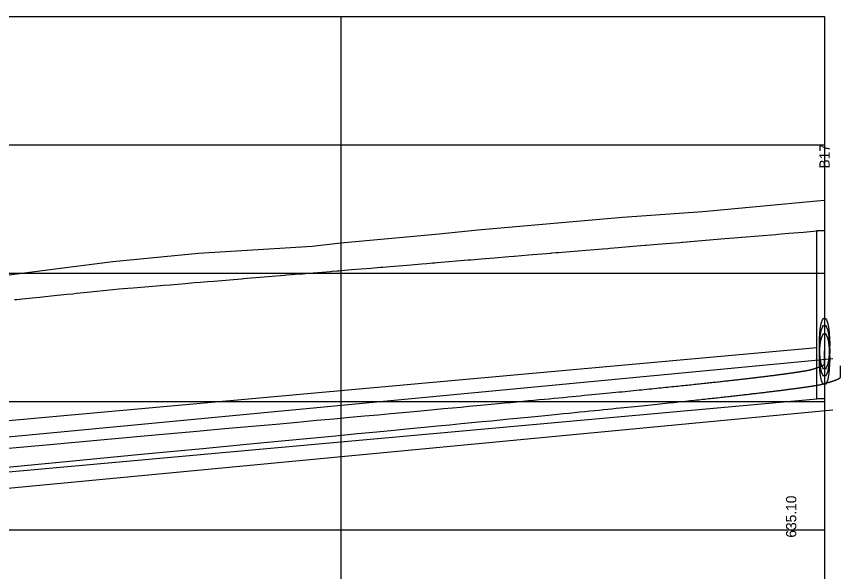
# Model space of a CAD drawing. Extents: x 2253035 to 2279930, y 13774972 to 13793443.
# Drawn here: x 2261163.2 to 2261323.8, y 13791365.4 to 13791473.6 of the extents above; entities that cross this region are included whole.
import ezdxf

# ---------------------------------------------------------------- set-up
doc = ezdxf.new("R2010")
doc.units = 0
for name, color, linetype in [('Default', 7, 'Continuous'), ('E_Utility_ATT_HH', 7, 'Continuous'), ('E_Utility_ATT_PR_PVC', 7, 'Continuous'), ('E_Utillity_Water_Water Line_12in', 7, 'Continuous'), ('E_Utillity_Water_Water Line_1in', 7, 'Continuous'), ('E_Utillity_Water_Water Line_4in', 7, 'Continuous'), ('E_Utillity_Water_Water Line_8in', 7, 'Continuous')]:
    doc.layers.add(name, color=color, linetype=linetype)

msp = doc.modelspace()

# ---------------------------------------------------------------- linework, layer by layer
at = {"layer": 'Default'}
for p, q in [((2261226.46, 13791298.56), (2261226.46, 13791473.56)), ((2260026.46, 13791448.56), (2261320.64, 13791448.56)), ((2260026.46, 13791423.56), (2261320.64, 13791423.56)), ((2260026.46, 13791398.56), (2261320.64, 13791398.56)), ((2260026.46, 13791373.56), (2261320.64, 13791373.56))]:
    msp.add_line(p, q, dxfattribs=at)
msp.add_lwpolyline([(2260026.46, 13791298.56), (2260026.46, 13791473.56), (2261320.64, 13791473.56), (2261320.64, 13791298.56)], close=True, dxfattribs=at)
at = {"layer": 'E_Utility_ATT_PR_PVC'}
for points in [[(2261151.51, 13791388.53), (2261169, 13791390.11), (2261181.06, 13791391.2), (2261190.23, 13791392.03), (2261197.64, 13791392.7), (2261203.84, 13791393.27), (2261209.16, 13791393.75), (2261213.82, 13791394.17), (2261217.97, 13791394.55), (2261221.7, 13791394.89), (2261225.08, 13791395.2), (2261228.18, 13791395.49), (2261231.04, 13791395.75), (2261233.69, 13791395.99), (2261236.15, 13791396.22), (2261238.46, 13791396.43), (2261240.63, 13791396.63), (2261242.67, 13791396.82), (2261244.59, 13791397), (2261246.42, 13791397.17), (2261248.16, 13791397.33), (2261249.81, 13791397.48), (2261251.38, 13791397.63), (2261252.89, 13791397.77), (2261254.33, 13791397.91), (2261255.71, 13791398.03), (2261257.04, 13791398.16), (2261258.31, 13791398.28), (2261259.54, 13791398.39), (2261260.73, 13791398.51), (2261261.87, 13791398.61), (2261262.97, 13791398.72), (2261264.04, 13791398.82), (2261265.07, 13791398.92), (2261266.07, 13791399.01), (2261267.03, 13791399.1), (2261267.97, 13791399.19), (2261268.88, 13791399.28), (2261269.77, 13791399.36), (2261270.63, 13791399.45), (2261271.46, 13791399.53), (2261272.28, 13791399.61), (2261273.07, 13791399.68), (2261273.84, 13791399.76), (2261274.59, 13791399.83), (2261275.33, 13791399.9), (2261276.04, 13791399.97), (2261276.74, 13791400.04), (2261277.42, 13791400.1), (2261278.08, 13791400.17), (2261278.73, 13791400.23), (2261279.37, 13791400.29), (2261279.99, 13791400.35), (2261280.6, 13791400.41), (2261281.19, 13791400.47), (2261281.78, 13791400.53), (2261282.35, 13791400.59), (2261282.9, 13791400.64), (2261283.45, 13791400.7), (2261283.99, 13791400.75), (2261284.51, 13791400.8), (2261285.02, 13791400.85), (2261285.53, 13791400.9), (2261286.02, 13791400.95), (2261286.51, 13791401), (2261286.99, 13791401.05), (2261287.45, 13791401.1), (2261287.91, 13791401.14), (2261288.36, 13791401.19), (2261288.81, 13791401.23), (2261289.24, 13791401.28), (2261289.67, 13791401.32), (2261290.09, 13791401.36), (2261290.5, 13791401.41), (2261290.91, 13791401.45), (2261291.31, 13791401.49), (2261291.7, 13791401.53), (2261292.09, 13791401.57), (2261292.47, 13791401.61), (2261292.84, 13791401.65), (2261293.21, 13791401.68), (2261293.57, 13791401.72), (2261293.92, 13791401.76), (2261294.28, 13791401.8), (2261294.62, 13791401.83), (2261294.96, 13791401.87), (2261295.29, 13791401.9), (2261295.62, 13791401.94), (2261295.95, 13791401.97), (2261296.27, 13791402), (2261296.58, 13791402.04), (2261296.89, 13791402.07), (2261297.2, 13791402.1), (2261297.5, 13791402.14), (2261297.8, 13791402.17), (2261298.09, 13791402.2), (2261298.38, 13791402.23), (2261298.66, 13791402.26), (2261298.94, 13791402.29), (2261299.22, 13791402.32), (2261299.49, 13791402.35), (2261299.76, 13791402.38), (2261300.02, 13791402.41), (2261300.29, 13791402.44), (2261300.54, 13791402.46), (2261300.8, 13791402.49), (2261301.05, 13791402.52), (2261301.3, 13791402.55), (2261301.54, 13791402.57), (2261301.78, 13791402.6), (2261302.02, 13791402.63), (2261302.26, 13791402.65), (2261302.49, 13791402.68), (2261302.72, 13791402.7), (2261302.94, 13791402.73), (2261303.17, 13791402.76), (2261303.39, 13791402.78), (2261303.6, 13791402.8), (2261303.82, 13791402.83), (2261304.03, 13791402.85), (2261304.24, 13791402.88), (2261304.45, 13791402.9), (2261304.65, 13791402.92), (2261304.85, 13791402.95), (2261305.05, 13791402.97), (2261305.25, 13791402.99), (2261305.44, 13791403.02), (2261305.63, 13791403.04), (2261305.82, 13791403.06), (2261306.01, 13791403.08), (2261306.2, 13791403.1), (2261306.38, 13791403.12), (2261306.56, 13791403.15), (2261306.74, 13791403.17), (2261306.91, 13791403.19), (2261307.09, 13791403.21), (2261307.26, 13791403.23), (2261307.43, 13791403.25), (2261307.6, 13791403.27), (2261307.76, 13791403.29), (2261307.93, 13791403.31), (2261308.09, 13791403.33), (2261308.25, 13791403.35), (2261308.41, 13791403.37), (2261308.57, 13791403.39), (2261308.72, 13791403.41), (2261308.87, 13791403.42), (2261309.03, 13791403.44), (2261309.18, 13791403.46), (2261309.32, 13791403.48), (2261309.47, 13791403.5), (2261309.61, 13791403.52), (2261309.76, 13791403.53), (2261309.9, 13791403.55), (2261310.04, 13791403.57), (2261310.18, 13791403.59), (2261310.31, 13791403.6), (2261310.45, 13791403.62), (2261310.58, 13791403.64), (2261310.71, 13791403.65), (2261310.84, 13791403.67), (2261310.97, 13791403.69), (2261311.1, 13791403.7), (2261311.23, 13791403.72), (2261311.35, 13791403.74), (2261311.47, 13791403.75), (2261311.6, 13791403.77), (2261311.72, 13791403.79), (2261311.84, 13791403.8), (2261311.95, 13791403.82), (2261312.07, 13791403.83), (2261312.19, 13791403.85), (2261312.3, 13791403.86), (2261312.41, 13791403.88), (2261312.53, 13791403.89), (2261312.64, 13791403.91), (2261312.75, 13791403.92), (2261312.85, 13791403.94), (2261312.96, 13791403.95), (2261313.07, 13791403.97), (2261313.17, 13791403.98), (2261313.27, 13791404), (2261313.38, 13791404.01), (2261313.48, 13791404.02), (2261313.58, 13791404.04), (2261313.68, 13791404.05), (2261313.77, 13791404.06), (2261313.87, 13791404.08), (2261313.97, 13791404.09), (2261314.06, 13791404.11), (2261314.15, 13791404.12), (2261314.25, 13791404.13), (2261314.34, 13791404.15), (2261314.43, 13791404.16), (2261314.52, 13791404.17), (2261314.61, 13791404.18), (2261314.69, 13791404.2), (2261314.78, 13791404.21), (2261314.86, 13791404.22), (2261314.95, 13791404.24), (2261315.03, 13791404.25), (2261315.12, 13791404.26), (2261315.2, 13791404.27), (2261315.28, 13791404.29), (2261315.36, 13791404.3), (2261315.44, 13791404.31), (2261315.52, 13791404.32), (2261315.59, 13791404.33), (2261315.67, 13791404.35), (2261315.75, 13791404.36), (2261315.82, 13791404.37), (2261315.89, 13791404.38), (2261315.97, 13791404.39), (2261316.04, 13791404.4), (2261316.11, 13791404.42), (2261316.18, 13791404.43), (2261316.25, 13791404.44), (2261316.32, 13791404.45), (2261316.39, 13791404.46), (2261316.46, 13791404.47), (2261316.52, 13791404.48), (2261316.59, 13791404.49), (2261316.66, 13791404.5), (2261316.72, 13791404.52), (2261316.78, 13791404.53), (2261316.85, 13791404.54), (2261316.91, 13791404.55), (2261316.97, 13791404.56), (2261317.03, 13791404.57), (2261317.09, 13791404.58), (2261317.15, 13791404.59), (2261317.21, 13791404.6), (2261317.27, 13791404.61), (2261317.33, 13791404.62), (2261317.38, 13791404.63), (2261317.44, 13791404.64), (2261317.5, 13791404.65), (2261317.55, 13791404.66), (2261317.6, 13791404.67), (2261317.66, 13791404.68), (2261317.71, 13791404.7), (2261317.76, 13791404.71), (2261317.81, 13791404.72), (2261317.87, 13791404.74), (2261317.92, 13791404.75), (2261317.97, 13791404.77), (2261318.02, 13791404.78), (2261318.06, 13791404.79), (2261318.11, 13791404.81), (2261318.16, 13791404.82), (2261318.21, 13791404.83), (2261318.25, 13791404.85), (2261318.3, 13791404.86), (2261318.34, 13791404.87), (2261318.39, 13791404.89), (2261318.43, 13791404.9), (2261318.47, 13791404.91), (2261318.52, 13791404.93), (2261318.56, 13791404.94), (2261318.6, 13791404.95), (2261318.64, 13791404.96), (2261318.68, 13791404.98), (2261318.72, 13791404.99), (2261318.76, 13791405), (2261318.8, 13791405.01), (2261318.84, 13791405.02), (2261318.88, 13791405.04), (2261318.92, 13791405.05), (2261318.95, 13791405.06), (2261318.99, 13791405.07), (2261319.03, 13791405.08), (2261319.06, 13791405.09), (2261319.1, 13791405.11), (2261319.13, 13791405.12), (2261319.17, 13791405.13), (2261319.2, 13791405.14), (2261319.23, 13791405.15), (2261319.27, 13791405.16), (2261319.3, 13791405.17), (2261319.33, 13791405.18), (2261319.36, 13791405.19), (2261319.39, 13791405.2), (2261319.42, 13791405.21), (2261319.45, 13791405.22), (2261319.48, 13791405.23), (2261319.51, 13791405.24), (2261319.54, 13791405.25), (2261319.57, 13791405.26), (2261319.59, 13791405.27), (2261319.62, 13791405.28), (2261319.65, 13791405.29), (2261319.67, 13791405.3), (2261319.7, 13791405.31), (2261319.73, 13791405.32), (2261319.75, 13791405.33), (2261319.78, 13791405.34), (2261319.8, 13791405.35), (2261319.82, 13791405.36), (2261319.85, 13791405.37), (2261319.87, 13791405.38), (2261319.89, 13791405.39), (2261319.92, 13791405.4), (2261319.94, 13791405.41), (2261319.96, 13791405.42), (2261319.98, 13791405.42), (2261320, 13791405.43), (2261320.02, 13791405.44), (2261320.04, 13791405.45), (2261320.06, 13791405.46), (2261320.08, 13791405.47), (2261320.1, 13791405.48), (2261320.12, 13791405.48), (2261320.14, 13791405.49), (2261320.15, 13791405.5), (2261320.17, 13791405.51), (2261320.19, 13791405.52), (2261320.21, 13791405.52), (2261320.22, 13791405.53), (2261320.24, 13791405.54), (2261320.25, 13791405.55), (2261320.27, 13791405.56), (2261320.28, 13791405.56), (2261320.3, 13791405.57), (2261320.31, 13791405.58), (2261320.33, 13791405.59), (2261320.34, 13791405.59), (2261320.35, 13791405.6), (2261320.37, 13791405.61), (2261320.38, 13791405.62), (2261320.39, 13791405.62), (2261320.4, 13791405.63), (2261320.42, 13791405.64), (2261320.43, 13791405.64), (2261320.44, 13791405.65), (2261320.45, 13791405.66), (2261320.46, 13791405.67), (2261320.47, 13791405.67), (2261320.48, 13791405.68), (2261320.49, 13791405.69), (2261320.5, 13791405.69), (2261320.51, 13791405.7), (2261320.52, 13791405.71), (2261320.52, 13791405.71), (2261320.53, 13791405.72), (2261320.54, 13791405.72), (2261320.55, 13791405.73), (2261320.55, 13791405.74), (2261320.56, 13791405.74), (2261320.57, 13791405.75), (2261320.57, 13791405.76), (2261320.58, 13791405.76), (2261320.59, 13791405.77), (2261320.59, 13791405.77), (2261320.6, 13791405.78), (2261320.6, 13791405.79), (2261320.61, 13791405.79), (2261320.61, 13791405.8), (2261320.61, 13791405.8), (2261320.62, 13791405.81), (2261320.62, 13791405.81), (2261320.62, 13791405.82), (2261320.63, 13791405.83), (2261320.63, 13791405.83), (2261320.63, 13791405.84), (2261320.63, 13791405.84), (2261320.64, 13791405.85), (2261320.64, 13791405.85), (2261320.64, 13791405.86), (2261320.64, 13791405.86), (2261320.64, 13791405.87), (2261320.64, 13791405.87), (2261320.64, 13791405.88), (2261320.64, 13791405.88), (2261320.64, 13791408.44)], [(2261139.69, 13791383.71), (2261171.58, 13791386.75), (2261188.27, 13791388.33), (2261199.55, 13791389.41), (2261208.05, 13791390.22), (2261214.86, 13791390.87), (2261220.54, 13791391.42), (2261225.4, 13791391.88), (2261229.65, 13791392.29), (2261233.41, 13791392.65), (2261236.8, 13791392.98), (2261239.87, 13791393.28), (2261242.67, 13791393.55), (2261245.25, 13791393.8), (2261247.65, 13791394.03), (2261249.87, 13791394.25), (2261251.95, 13791394.45), (2261253.9, 13791394.64), (2261255.74, 13791394.82), (2261257.48, 13791394.99), (2261259.12, 13791395.15), (2261260.68, 13791395.3), (2261262.16, 13791395.45), (2261263.58, 13791395.59), (2261264.93, 13791395.72), (2261266.22, 13791395.85), (2261267.46, 13791395.97), (2261268.65, 13791396.09), (2261269.79, 13791396.2), (2261270.89, 13791396.31), (2261271.95, 13791396.42), (2261272.97, 13791396.52), (2261273.96, 13791396.62), (2261274.91, 13791396.71), (2261275.83, 13791396.8), (2261276.72, 13791396.89), (2261277.59, 13791396.98), (2261278.43, 13791397.07), (2261279.24, 13791397.15), (2261280.03, 13791397.23), (2261280.8, 13791397.31), (2261281.54, 13791397.38), (2261282.27, 13791397.46), (2261282.97, 13791397.53), (2261283.66, 13791397.6), (2261284.33, 13791397.67), (2261284.98, 13791397.73), (2261285.62, 13791397.8), (2261286.24, 13791397.86), (2261286.84, 13791397.92), (2261287.43, 13791397.99), (2261288.01, 13791398.05), (2261288.57, 13791398.1), (2261289.13, 13791398.16), (2261289.67, 13791398.22), (2261290.19, 13791398.27), (2261290.71, 13791398.33), (2261291.21, 13791398.38), (2261291.71, 13791398.43), (2261292.19, 13791398.48), (2261292.67, 13791398.53), (2261293.13, 13791398.58), (2261293.59, 13791398.63), (2261294.03, 13791398.68), (2261294.47, 13791398.72), (2261294.9, 13791398.77), (2261295.32, 13791398.81), (2261295.74, 13791398.86), (2261296.14, 13791398.9), (2261296.54, 13791398.95), (2261296.93, 13791398.99), (2261297.31, 13791399.03), (2261297.69, 13791399.07), (2261298.06, 13791399.11), (2261298.42, 13791399.15), (2261298.78, 13791399.19), (2261299.13, 13791399.23), (2261299.48, 13791399.26), (2261299.82, 13791399.3), (2261300.15, 13791399.34), (2261300.48, 13791399.37), (2261300.8, 13791399.41), (2261301.12, 13791399.45), (2261301.44, 13791399.48), (2261301.74, 13791399.51), (2261302.05, 13791399.55), (2261302.34, 13791399.58), (2261302.64, 13791399.61), (2261302.93, 13791399.65), (2261303.21, 13791399.68), (2261303.49, 13791399.71), (2261303.77, 13791399.74), (2261304.04, 13791399.77), (2261304.3, 13791399.8), (2261304.57, 13791399.83), (2261304.83, 13791399.86), (2261305.08, 13791399.89), (2261305.34, 13791399.92), (2261305.58, 13791399.95), (2261305.83, 13791399.98), (2261306.07, 13791400), (2261306.31, 13791400.03), (2261306.54, 13791400.06), (2261306.77, 13791400.09), (2261307, 13791400.11), (2261307.23, 13791400.14), (2261307.45, 13791400.17), (2261307.67, 13791400.19), (2261307.88, 13791400.22), (2261308.1, 13791400.24), (2261308.3, 13791400.27), (2261308.51, 13791400.29), (2261308.72, 13791400.32), (2261308.92, 13791400.34), (2261309.12, 13791400.36), (2261309.31, 13791400.39), (2261309.51, 13791400.41), (2261309.7, 13791400.43), (2261309.88, 13791400.46), (2261310.07, 13791400.48), (2261310.25, 13791400.5), (2261310.44, 13791400.52), (2261310.61, 13791400.55), (2261310.79, 13791400.57), (2261310.97, 13791400.59), (2261311.14, 13791400.61), (2261311.31, 13791400.63), (2261311.47, 13791400.65), (2261311.64, 13791400.67), (2261311.8, 13791400.69), (2261311.96, 13791400.71), (2261312.12, 13791400.73), (2261312.28, 13791400.75), (2261312.44, 13791400.77), (2261312.59, 13791400.79), (2261312.74, 13791400.81), (2261312.89, 13791400.83), (2261313.04, 13791400.85), (2261313.19, 13791400.87), (2261313.33, 13791400.89), (2261313.47, 13791400.91), (2261313.61, 13791400.93), (2261313.75, 13791400.94), (2261313.89, 13791400.96), (2261314.03, 13791400.98), (2261314.16, 13791401), (2261314.29, 13791401.01), (2261314.42, 13791401.03), (2261314.55, 13791401.05), (2261314.68, 13791401.07), (2261314.81, 13791401.08), (2261314.93, 13791401.1), (2261315.05, 13791401.12), (2261315.18, 13791401.13), (2261315.3, 13791401.15), (2261315.42, 13791401.17), (2261315.53, 13791401.18), (2261315.65, 13791401.2), (2261315.76, 13791401.21), (2261315.88, 13791401.23), (2261315.99, 13791401.25), (2261316.1, 13791401.26), (2261316.21, 13791401.28), (2261316.32, 13791401.29), (2261316.42, 13791401.31), (2261316.53, 13791401.32), (2261316.63, 13791401.34), (2261316.74, 13791401.35), (2261316.84, 13791401.37), (2261316.94, 13791401.38), (2261317.04, 13791401.4), (2261317.14, 13791401.41), (2261317.23, 13791401.42), (2261317.33, 13791401.44), (2261317.43, 13791401.45), (2261317.52, 13791401.47), (2261317.61, 13791401.48), (2261317.7, 13791401.49), (2261317.79, 13791401.51), (2261317.88, 13791401.52), (2261317.97, 13791401.53), (2261318.06, 13791401.55), (2261318.15, 13791401.56), (2261318.23, 13791401.57), (2261318.32, 13791401.59), (2261318.4, 13791401.6), (2261318.48, 13791401.61), (2261318.56, 13791401.63), (2261318.64, 13791401.64), (2261318.72, 13791401.65), (2261318.8, 13791401.66), (2261318.88, 13791401.68), (2261318.96, 13791401.69), (2261319.03, 13791401.7), (2261319.11, 13791401.71), (2261319.18, 13791401.72), (2261319.25, 13791401.74), (2261319.33, 13791401.75), (2261319.4, 13791401.76), (2261319.47, 13791401.77), (2261319.54, 13791401.78), (2261319.61, 13791401.79), (2261319.68, 13791401.81), (2261319.74, 13791401.82), (2261319.81, 13791401.83), (2261319.88, 13791401.85), (2261319.94, 13791401.87), (2261320, 13791401.89), (2261320.07, 13791401.9), (2261320.13, 13791401.92), (2261320.19, 13791401.94), (2261320.25, 13791401.95), (2261320.31, 13791401.97), (2261320.37, 13791401.99), (2261320.43, 13791402), (2261320.49, 13791402.02), (2261320.55, 13791402.03), (2261320.6, 13791402.05), (2261320.66, 13791402.07), (2261320.72, 13791402.08), (2261320.77, 13791402.1), (2261320.82, 13791402.11), (2261320.88, 13791402.13), (2261320.93, 13791402.14), (2261320.98, 13791402.16), (2261321.03, 13791402.17), (2261321.08, 13791402.19), (2261321.13, 13791402.2), (2261321.18, 13791402.21), (2261321.23, 13791402.23), (2261321.28, 13791402.24), (2261321.33, 13791402.26), (2261321.38, 13791402.27), (2261321.42, 13791402.29), (2261321.47, 13791402.3), (2261321.51, 13791402.31), (2261321.56, 13791402.33), (2261321.6, 13791402.34), (2261321.64, 13791402.35), (2261321.69, 13791402.37), (2261321.73, 13791402.38), (2261321.77, 13791402.39), (2261321.81, 13791402.4), (2261321.85, 13791402.42), (2261321.89, 13791402.43), (2261321.93, 13791402.44), (2261321.97, 13791402.45), (2261322.01, 13791402.47), (2261322.05, 13791402.48), (2261322.08, 13791402.49), (2261322.12, 13791402.5), (2261322.16, 13791402.51), (2261322.19, 13791402.53), (2261322.23, 13791402.54), (2261322.26, 13791402.55), (2261322.3, 13791402.56), (2261322.33, 13791402.57), (2261322.36, 13791402.58), (2261322.4, 13791402.6), (2261322.43, 13791402.61), (2261322.46, 13791402.62), (2261322.49, 13791402.63), (2261322.52, 13791402.64), (2261322.55, 13791402.65), (2261322.58, 13791402.66), (2261322.61, 13791402.67), (2261322.64, 13791402.68), (2261322.67, 13791402.69), (2261322.7, 13791402.7), (2261322.73, 13791402.71), (2261322.75, 13791402.72), (2261322.78, 13791402.73), (2261322.81, 13791402.74), (2261322.83, 13791402.75), (2261322.86, 13791402.76), (2261322.88, 13791402.77), (2261322.91, 13791402.78), (2261322.93, 13791402.79), (2261322.96, 13791402.8), (2261322.98, 13791402.81), (2261323, 13791402.82), (2261323.03, 13791402.83), (2261323.05, 13791402.84), (2261323.07, 13791402.85), (2261323.09, 13791402.86), (2261323.11, 13791402.87), (2261323.13, 13791402.87), (2261323.15, 13791402.88), (2261323.17, 13791402.89), (2261323.19, 13791402.9), (2261323.21, 13791402.91), (2261323.23, 13791402.92), (2261323.25, 13791402.93), (2261323.27, 13791402.93), (2261323.28, 13791402.94), (2261323.3, 13791402.95), (2261323.32, 13791402.96), (2261323.33, 13791402.97), (2261323.35, 13791402.98), (2261323.37, 13791402.98), (2261323.38, 13791402.99), (2261323.4, 13791403), (2261323.41, 13791403.01), (2261323.42, 13791403.02), (2261323.44, 13791403.02), (2261323.45, 13791403.03), (2261323.47, 13791403.04), (2261323.48, 13791403.05), (2261323.49, 13791403.05), (2261323.5, 13791403.06), (2261323.52, 13791403.07), (2261323.53, 13791403.07), (2261323.54, 13791403.08), (2261323.55, 13791403.09), (2261323.56, 13791403.1), (2261323.57, 13791403.1), (2261323.58, 13791403.11), (2261323.59, 13791403.12), (2261323.6, 13791403.12), (2261323.61, 13791403.13), (2261323.62, 13791403.14), (2261323.63, 13791403.14), (2261323.64, 13791403.15), (2261323.64, 13791403.16), (2261323.65, 13791403.16), (2261323.66, 13791403.17), (2261323.67, 13791403.18), (2261323.67, 13791403.18), (2261323.68, 13791403.19), (2261323.69, 13791403.19), (2261323.69, 13791403.2), (2261323.7, 13791403.21), (2261323.7, 13791403.21), (2261323.71, 13791403.22), (2261323.71, 13791403.22), (2261323.72, 13791403.23), (2261323.72, 13791403.24), (2261323.72, 13791403.24), (2261323.73, 13791403.25), (2261323.73, 13791403.25), (2261323.74, 13791403.26), (2261323.74, 13791403.26), (2261323.74, 13791403.27), (2261323.74, 13791403.28), (2261323.75, 13791403.28), (2261323.75, 13791403.29), (2261323.75, 13791403.29), (2261323.75, 13791403.3), (2261323.75, 13791403.3), (2261323.75, 13791403.31), (2261323.75, 13791403.31), (2261323.75, 13791403.32), (2261323.75, 13791403.32), (2261323.75, 13791405.49)]]:
    msp.add_lwpolyline(points, dxfattribs=at)
at = {"layer": 'E_Utillity_Water_Water Line_12in'}
msp.add_lwpolyline([(2261319.14, 13791431.89), (2261320.64, 13791431.89), (2261320.64, 13791399.06), (2261319.14, 13791399.06)], close=True, dxfattribs=at)
at = {"layer": 'E_Utillity_Water_Water Line_1in'}
msp.add_lwpolyline([(2261154.23, 13791422.28), (2261171.85, 13791424.51), (2261182, 13791425.81), (2261198.68, 13791427.43), (2261220.82, 13791428.82), (2261226.41, 13791429.49), (2261245.56, 13791431.19), (2261253.12, 13791432.01), (2261281.26, 13791434.46), (2261296.91, 13791435.59), (2261319.14, 13791437.65), (2261319.14, 13791437.65), (2261320.64, 13791437.79)], dxfattribs=at)
at = {"layer": 'E_Utillity_Water_Water Line_4in'}
for p, q in [((2260993.21, 13791379.72), (2261319.14, 13791409.06)), ((2261009.3, 13791377.21), (2261322.25, 13791406.91)), ((2260993.21, 13791369.72), (2261319.14, 13791399.06)), ((2261009.3, 13791367.21), (2261322.25, 13791396.91))]:
    msp.add_line(p, q, dxfattribs=at)
for centre in [(2261320.64, 13791409.83), (2261320.64, 13791408.43), (2261320.64, 13791406.82)]:
    msp.add_ellipse(centre, major_axis=(0, 5), ratio=0.2, dxfattribs=at)
at = {"layer": 'E_Utillity_Water_Water Line_8in'}
msp.add_lwpolyline([(2261162.88, 13791418.4), (2261163.28, 13791418.45), (2261164.37, 13791418.56), (2261167.75, 13791418.9), (2261171.15, 13791419.25), (2261171.89, 13791419.32), (2261173.07, 13791419.44), (2261174.19, 13791419.56), (2261174.96, 13791419.64), (2261177.02, 13791419.85), (2261182.01, 13791420.35), (2261183.27, 13791420.48), (2261184.08, 13791420.56), (2261184.92, 13791420.63), (2261185.94, 13791420.71), (2261191.29, 13791421.16), (2261191.88, 13791421.2), (2261193.2, 13791421.31), (2261196.12, 13791421.56), (2261197.95, 13791421.71), (2261199.01, 13791421.8), (2261200.43, 13791421.91), (2261201.69, 13791422.02), (2261207.05, 13791422.46), (2261207.56, 13791422.51), (2261208.17, 13791422.56), (2261208.98, 13791422.62), (2261209.87, 13791422.7), (2261212.27, 13791422.9), (2261215.45, 13791423.16), (2261215.89, 13791423.2), (2261216.73, 13791423.27), (2261217.53, 13791423.33), (2261218.39, 13791423.41), (2261218.98, 13791423.45), (2261220.21, 13791423.56), (2261222.81, 13791423.77), (2261224.4, 13791423.9), (2261224.76, 13791423.93), (2261225.74, 13791424.02), (2261226.08, 13791424.04), (2261226.57, 13791424.08), (2261228.49, 13791424.24), (2261232.25, 13791424.56), (2261234.08, 13791424.71), (2261234.63, 13791424.75), (2261236.03, 13791424.87), (2261240.09, 13791425.21), (2261242.15, 13791425.38), (2261243.18, 13791425.46), (2261244.3, 13791425.56), (2261244.7, 13791425.59), (2261245.21, 13791425.63), (2261251.22, 13791426.13), (2261251.73, 13791426.17), (2261252.47, 13791426.24), (2261253.77, 13791426.34), (2261256.34, 13791426.56), (2261259.14, 13791426.79), (2261260.12, 13791426.87), (2261260.28, 13791426.88), (2261262.95, 13791427.11), (2261267.33, 13791427.47), (2261267.54, 13791427.49), (2261268.38, 13791427.56), (2261268.78, 13791427.59), (2261268.83, 13791427.59), (2261268.83, 13791427.59), (2261270.31, 13791427.72), (2261273.4, 13791427.97), (2261277.37, 13791428.3), (2261278.43, 13791428.39), (2261278.85, 13791428.43), (2261280.43, 13791428.56), (2261284.06, 13791428.86), (2261285.65, 13791428.99), (2261285.92, 13791429.01), (2261288.05, 13791429.19), (2261292.47, 13791429.56), (2261292.92, 13791429.59), (2261293.03, 13791429.6), (2261294.47, 13791429.72), (2261294.53, 13791429.73), (2261295.93, 13791429.84), (2261301.19, 13791430.28), (2261303.02, 13791430.43), (2261304.45, 13791430.55), (2261304.47, 13791430.55), (2261304.51, 13791430.56), (2261311.15, 13791431.11), (2261311.57, 13791431.14), (2261312.19, 13791431.19), (2261313.67, 13791431.32), (2261316.56, 13791431.56), (2261319.14, 13791431.77), (2261319.14, 13791431.77), (2261319.26, 13791431.78), (2261320.12, 13791431.85), (2261320.27, 13791431.86), (2261320.64, 13791431.89)], dxfattribs=at)

# ---------------------------------------------------------------- texts
at = {"layer": 'E_Utility_ATT_HH'}
for s, p in [('B17', (2261321.64, 13791443.93)), ('635.10', (2261315.14, 13791372.04))]:
    msp.add_text(s, height=2, rotation=90, dxfattribs=at).set_placement(p)

doc.saveas('drawing.dxf')
